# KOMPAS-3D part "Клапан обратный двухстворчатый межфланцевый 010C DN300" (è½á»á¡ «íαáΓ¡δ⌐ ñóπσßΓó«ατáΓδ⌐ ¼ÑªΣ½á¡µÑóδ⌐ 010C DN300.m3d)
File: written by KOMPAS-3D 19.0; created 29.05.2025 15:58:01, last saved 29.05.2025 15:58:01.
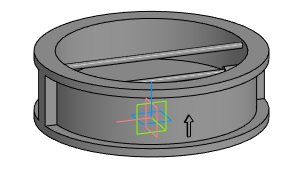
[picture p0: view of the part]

Document properties: Полное имя файла: E:\Dendor Работа Сачек\3D для проекитирвщиков\5.2 Тип 010C, 010C.Y Клапан обратный двухстворчатый межфланцевый\stp_Клапан обратный двухстворчатый межфланцевый 010C\Клапан обратный двухстворчатый межфланцевый 010C DN300.m3d

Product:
- Part/product: Клапан обратный двухстворчатый межфланцевый 010C DN300

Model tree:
1. Операция без истории:1  (labels: Клапан обратный двухстворчатый межфланцевый 010C DN300)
